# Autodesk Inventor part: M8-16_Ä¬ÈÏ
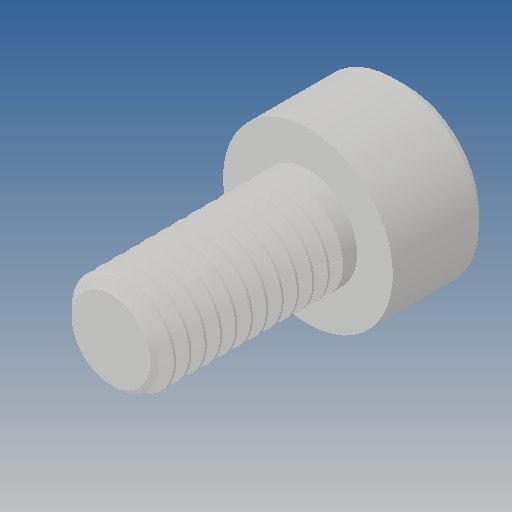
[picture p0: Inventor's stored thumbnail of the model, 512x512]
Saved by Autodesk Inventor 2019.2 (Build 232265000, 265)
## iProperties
Created: 2010-06
Part Number: M8-16_Ä¬ÈÏ
Material: Ogólny
Document SubType Name: Modeling
Designer: CADENGINEERING4
Density: 1 g/cm^3
Appearance: Domyślna
Author: CADENGINEERING4
Revision Number: ÈÎºÎ
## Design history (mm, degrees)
feature "NONE"
node "Bryła1"
